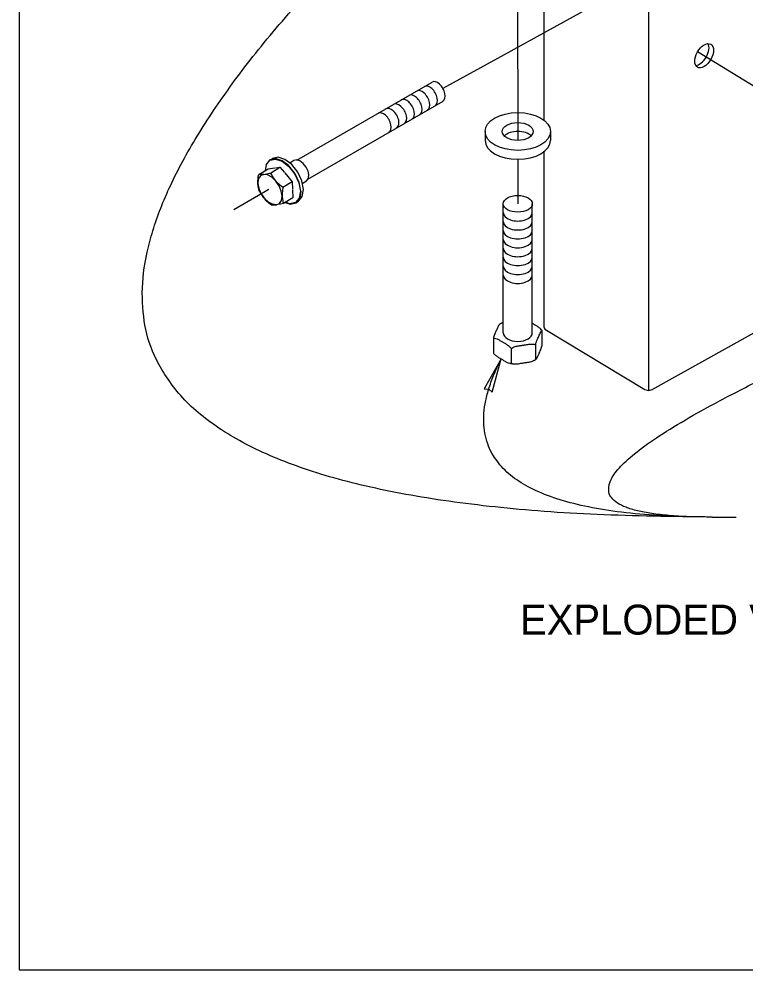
# Model space of a CAD drawing. Extents: x 99862 to 103151, y 99997 to 117076.
# Drawn here: x 99862 to 100348, y 112000 to 112634 of the extents above; entities that cross this region are included whole.
import ezdxf

# ---------------------------------------------------------------- set-up
doc = ezdxf.new("R2010")
doc.units = 0
for name, color, linetype in [('Level 1', 7, 'Continuous'), ('Level 12', 7, 'Continuous'), ('Level 13', 7, 'Continuous'), ('Level 15', 7, 'Continuous'), ('Level 20', 7, 'Continuous'), ('Level 3', 7, 'Continuous'), ('Level 4', 7, 'Continuous'), ('Level 5', 7, 'Continuous'), ('Level 60', 7, 'Continuous'), ('Level 9', 7, 'Continuous')]:
    doc.layers.add(name, color=color, linetype=linetype)

msp = doc.modelspace()

# ---------------------------------------------------------------- linework, layer by layer
at = {"layer": 'Level 1'}
msp.add_lwpolyline([(99862, 111999.5), (103151, 111999.5), (103151, 114075.5), (99862, 114075.5)], close=True, dxfattribs=at)
at = {"layer": 'Level 12'}
for p, q in [((100173.34, 112559.31), (100173.34, 112553.37)), ((100217.04, 112559.31), (100217.04, 112553.37)), ((100185.48, 112424.8), (100185.48, 112511.05)), ((100204.9, 112424.8), (100204.9, 112511.05)), ((100211.44, 112416.42), (100211.44, 112426.33)), ((100178.94, 112421.3), (100178.94, 112411.39)), ((100190.84, 112414.43), (100190.84, 112404.52)), ((100207.09, 112416.95), (100207.09, 112407.03))]:
    msp.add_line(p, q, dxfattribs=at)
for centre, major_axis in [((100195.19, 112559.31), (-21.85, 0)), ((100195.19, 112559.31), (-10.32, 0)), ((100195.19, 112511.05), (-9.71, 0))]:
    msp.add_ellipse(centre, major_axis=major_axis, ratio=0.57735, dxfattribs=at)
for centre, major_axis, start_param, end_param in [((100195.19, 112553.37), (-10.32, 0), 3.664192, 5.760586), ((100195.19, 112553.37), (21.85, 0), 3.141593, 6.283185), ((100195.19, 112505.1), (9.71, 0), 3.141588, 6.283185), ((100195.19, 112499.15), (9.71, 0), 3.141588, 6.283185), ((100195.19, 112493.2), (9.71, 0), 3.141588, 6.283185), ((100195.19, 112487.26), (9.71, 0), 3.141588, 6.283185), ((100195.19, 112481.31), (9.71, 0), 3.141588, 6.283185), ((100195.19, 112475.36), (9.71, 0), 3.141588, 6.283185), ((100195.19, 112469.41), (9.71, 0), 3.141588, 6.283185), ((100195.19, 112463.47), (9.71, 0), 3.141588, 6.283185), ((100195.19, 112424.8), (9.71, 0), 3.141593, 6.283185)]:
    msp.add_ellipse(centre, major_axis=major_axis, ratio=0.57735, start_param=start_param, end_param=end_param, dxfattribs=at)
for points, degree in [([(100185.48, 112431.72), (100185.12, 112431.6), (100184.77, 112431.47), (100184.27, 112431.24), (100184.08, 112431.15), (100183.9, 112431.05)], 3), ([(100183.17, 112430.63), (100183.11, 112430.6), (100183.05, 112430.54), (100182.43, 112429.88), (100181.71, 112428.26), (100181.12, 112426.98), (100180.53, 112425.69), (100179.81, 112424.24), (100179.15, 112422.09), (100179.04, 112421.7), (100178.94, 112421.3)], 3), ([(100183.9, 112431.05), (100183.68, 112430.93), (100183.47, 112430.81), (100183.23, 112430.67), (100183.2, 112430.65), (100183.17, 112430.63)], 3), ([(100211.44, 112426.33), (100211.18, 112426.67), (100210.88, 112427), (100209.07, 112428.77), (100207.12, 112429.81), (100205.49, 112430.75), (100205.3, 112430.86), (100205.1, 112430.97), (100204.9, 112431.09)], 3), ([(100207.09, 112416.95), (100207.18, 112417.34), (100207.29, 112417.74), (100207.96, 112419.89), (100208.67, 112421.34), (100209.26, 112422.62), (100209.86, 112423.9), (100210.57, 112425.53), (100211.23, 112426.23), (100211.35, 112426.32), (100211.44, 112426.33)], 3), ([(100178.94, 112421.3), (100179.2, 112421.35), (100179.51, 112421.32), (100181.32, 112421), (100183.27, 112419.79), (100184.89, 112418.85), (100186.52, 112417.91), (100188.46, 112416.87), (100190.27, 112415.11), (100190.58, 112414.78), (100190.84, 112414.43)], 3), ([(100190.84, 112414.43), (100191.19, 112414.68), (100191.61, 112414.9), (100194.08, 112416), (100196.74, 112416.33), (100198.96, 112416.68), (100201.18, 112417.02), (100203.84, 112417.52), (100206.32, 112417.18), (100206.73, 112417.09), (100207.09, 112416.95)], 3), ([(100207.21, 112407.08), (100207.27, 112407.12), (100207.34, 112407.17), (100207.96, 112407.84), (100208.67, 112409.46), (100209.26, 112410.74), (100209.86, 112412.02), (100210.57, 112413.47), (100211.23, 112415.62), (100211.35, 112416.02), (100211.44, 112416.42)], 3), ([(100178.94, 112411.39), (100179.2, 112411.04), (100179.51, 112410.71), (100181.32, 112408.95), (100183.27, 112407.91), (100184.89, 112406.97), (100186.49, 112406.04), (100188.41, 112404.86), (100189.93, 112404.56)], 3), ([(100192.18, 112404.21), (100194.25, 112403.98), (100196.81, 112404.46), (100198.96, 112404.79), (100201.18, 112405.13), (100203.84, 112405.46), (100206.12, 112406.48), (100206.3, 112406.57), (100206.49, 112406.67)], 3), ([(100206.49, 112406.66), (100206.71, 112406.78), (100206.92, 112406.9), (100207.15, 112407.04), (100207.18, 112407.06), (100207.21, 112407.08)], 3), ([(100189.93, 112404.56), (100190.68, 112404.41), (100191.44, 112404.3), (100192.18, 112404.21)], 2)]:
    msp.add_open_spline(points, degree=degree, dxfattribs=at)
at = {"layer": 'Level 13'}
for p, q in [((100047.6, 112540.08), (100137.95, 112592.24)), ((100054.88, 112527.47), (100145.25, 112579.64))]:
    msp.add_line(p, q, dxfattribs=at)
for centre, end_param in [((100136.45, 112582.97), 9.424783), ((100141.6, 112585.95), 9.429517), ((100126.14, 112577.02), 9.424778), ((100131.3, 112580), 9.424778), ((100115.84, 112571.07), 9.42478), ((100120.99, 112574.04), 9.424784), ((100105.53, 112565.12), 9.424778), ((100110.68, 112568.09), 9.424778)]:
    msp.add_ellipse(centre, major_axis=(3.64, -6.31), ratio=0.57735, start_param=6.283185, end_param=end_param, dxfattribs=at)
at = {"layer": 'Level 15'}
for p, q in [((100194.87, 112812.71), (100195.15, 112553.35)), ((100252.09, 112646.72), (100181.73, 112608.09)), ((100385.2, 112569.71), (100315.22, 112612.39)), ((100181.73, 112608.09), (100145.24, 112588.06)), ((100195.16, 112540.75), (100195.19, 112511.05)), ((100005.57, 112507.23), (100028.93, 112520.74)), ((100325.17, 112301.86), (100341.17, 112301.86))]:
    msp.add_line(p, q, dxfattribs=at)
msp.add_lwpolyline([(100184.09, 112407.43), (100172.64, 112387.45), (100175.8, 112387.29), (100178.16, 112385.18)], close=True, dxfattribs=at)
for points in [[(100325.17, 112301.86), (99735.04, 112301.86), (100059.37, 112657.5)], [(100325.17, 112301.86), (100130.24, 112301.86), (100184.09, 112407.43)], [(100325.17, 112301.86), (100160.65, 112301.86), (100386.47, 112407.43)]]:
    msp.add_open_spline(points, degree=2, dxfattribs=at)
at = {"layer": 'Level 3'}
for p, q in [((100027.09, 112537.06), (100029.53, 112540.04)), ((100029.57, 112539.98), (100029.53, 112540.04)), ((100033.31, 112540.81), (100033.29, 112540.87)), ((100037.78, 112539.37), (100037.78, 112539.42)), ((100027.05, 112537.32), (100026.39, 112533.23)), ((100042.32, 112535.88), (100042.33, 112535.92)), ((100029.66, 112531.46), (100029.76, 112531.42)), ((100046.22, 112530.87), (100046.25, 112530.89)), ((100048.89, 112525.11), (100048.93, 112525.11)), ((100047.05, 112511.65), (100049.53, 112514.68)), ((100049.24, 112514.9), (100049.24, 112514.9)), ((100050.3, 112519.43), (100049.53, 112514.68)), ((100049.93, 112519.47), (100049.98, 112519.45)), ((100043.01, 112511.02), (100043.03, 112510.96)), ((100046.75, 112511.85), (100046.78, 112511.79))]:
    msp.add_line(p, q, dxfattribs=at)
for points in [[(100029.53, 112540.35), (100027.05, 112537.32), (100027.06, 112537.32)], [(100033.34, 112541.19), (100029.53, 112540.35), (100029.53, 112540.35)], [(100029.56, 112539.98), (100029.53, 112540.04), (100033.29, 112540.87)], [(100033.3, 112540.81), (100033.29, 112540.87), (100037.78, 112539.42)], [(100037.91, 112539.72), (100033.34, 112541.19), (100033.35, 112541.19)], [(100037.77, 112539.37), (100037.78, 112539.42), (100042.33, 112535.92)], [(100042.03, 112536.54), (100037.91, 112539.72)], [(100027.14, 112537.01), (100027.09, 112537.06), (100026.49, 112533.29)], [(100042.31, 112535.89), (100042.33, 112535.92), (100046.25, 112530.89)], [(100046.21, 112530.88), (100046.25, 112530.89), (100048.93, 112525.11)], [(100048.88, 112525.12), (100048.93, 112525.11), (100049.98, 112519.45)], [(100049.22, 112514.77), (100046.78, 112511.79), (100043.03, 112510.96)], [(100049.93, 112519.49), (100049.98, 112519.45), (100049.22, 112514.77)], [(100050.26, 112519.43), (100050.27, 112519.43), (100050.27, 112519.43), (100050.3, 112519.43)], [(100039.71, 112511.94), (100043.24, 112510.81), (100043.24, 112510.81)], [(100043.02, 112511.02), (100043.03, 112510.96), (100039.8, 112512)], [(100043.24, 112510.81), (100047.05, 112511.65), (100047.05, 112511.65)]]:
    msp.add_lwpolyline(points, dxfattribs=at)
at = {"layer": 'Level 4'}
msp.add_line((100282.77, 112386.45), (100282.77, 112659.75), dxfattribs=at)
for points in [[(100212.71, 112651.71), (100212.71, 112566.85)], [(100212.71, 112545.82), (100212.71, 112428.94), (100213.27, 112427.31), (100279.99, 112387), (100282.77, 112386.45), (100285, 112387), (100353.39, 112425.13), (100355.06, 112427.85)]]:
    msp.add_lwpolyline(points, dxfattribs=at)
msp.add_ellipse((100319.68, 112609.84), major_axis=(-4.45, -7.71), ratio=0.57735, dxfattribs=at)
msp.add_ellipse((100316.66, 112611.58), major_axis=(4.45, 7.71), ratio=0.57735, start_param=3.487884, end_param=5.936894, dxfattribs=at)
at = {"layer": 'Level 5'}
for p, q in [((100029.92, 112540.43), (100031.27, 112541.26)), ((100049.45, 112514.71), (100049.47, 112514.72))]:
    msp.add_line(p, q, dxfattribs=at)
for points in [[(100047.31, 112511.96), (100048.75, 112512.85), (100051.23, 112515.86), (100051.99, 112520.58), (100050.93, 112526.28), (100048.21, 112532.1), (100044.25, 112537.15), (100039.63, 112540.67), (100035.08, 112542.11), (100031.27, 112541.26)], [(100051.25, 112524.59), (100054.05, 112526.32), (100055.23, 112527.76), (100055.6, 112530.02), (100055.56, 112530.57), (100055.09, 112532.75), (100053.79, 112535.53), (100051.89, 112537.95), (100049.68, 112539.63), (100047.5, 112540.32), (100045.68, 112539.92), (100042.88, 112538.19)], [(100049.56, 112514.83), (100049.56, 112514.84), (100050.33, 112519.55), (100049.27, 112525.26), (100046.55, 112531.08), (100042.58, 112536.13), (100042.03, 112536.54)], [(100039.7, 112511.94), (100039.72, 112511.92), (100040.01, 112511.85)]]:
    msp.add_lwpolyline(points, dxfattribs=at)
at = {"layer": 'Level 60'}
msp.add_line((99862, 111999.5), (99862, 111999.5), dxfattribs=at)
msp.add_line((99862, 111999.5), (99862, 111999.5), dxfattribs=at)
at = {"layer": 'Level 9'}
msp.add_line((100030.07, 112531.54), (100036.33, 112535.4), dxfattribs=at)
msp.add_line((100030.07, 112531.54), (100036.33, 112535.4), dxfattribs=at)
for points in [[(100021.57, 112525.13), (100021.57, 112525.25), (100021.82, 112528.54), (100021.85, 112528.96), (100022.13, 112530.61), (100028.39, 112534.46), (100032.85, 112534.99)], [(100021.57, 112525.13), (100021.57, 112525.25), (100021.82, 112528.54), (100021.85, 112528.96), (100022.13, 112530.61), (100028.39, 112534.46), (100032.85, 112534.99)], [(100033.26, 112535.04), (100036.33, 112535.4), (100039.37, 112531.83)], [(100033.26, 112535.04), (100036.33, 112535.4), (100039.37, 112531.83)], [(100025.23, 112530.63), (100023.28, 112529.74), (100022, 112527.81), (100021.57, 112525.13)], [(100025.23, 112530.63), (100023.28, 112529.74), (100022, 112527.81), (100021.57, 112525.13)], [(100025.57, 112530.67), (100025.23, 112530.63), (100024.78, 112530.58), (100023.17, 112530.56), (100022.78, 112530.55), (100022.13, 112530.61)], [(100025.57, 112530.67), (100025.23, 112530.63), (100024.78, 112530.58), (100023.17, 112530.56), (100022.78, 112530.55), (100022.13, 112530.61)], [(100032.11, 112528.06), (100033.39, 112526.39), (100030.83, 112528.79), (100028.09, 112530.29), (100025.57, 112530.67), (100026.47, 112530.8), (100028.44, 112531.21), (100030.07, 112531.54), (100031.22, 112529.59), (100032.11, 112528.06)], [(100032.11, 112528.06), (100033.39, 112526.39), (100030.83, 112528.79), (100028.09, 112530.29), (100025.57, 112530.67), (100026.47, 112530.8), (100028.44, 112531.21), (100030.07, 112531.54), (100031.22, 112529.59), (100032.11, 112528.06)], [(100039.52, 112531.65), (100044.56, 112525.72), (100044.7, 112520.83)], [(100039.52, 112531.65), (100044.56, 112525.72), (100044.7, 112520.83)], [(100021.57, 112525.13), (100021.59, 112524.63), (100021.73, 112523.05), (100022.06, 112521.61), (100022.43, 112520)], [(100022.43, 112520), (100022.06, 112521.61), (100021.73, 112523.05), (100021.59, 112524.63), (100021.57, 112525.13)], [(100021.59, 112524.63), (100022.18, 112521.38), (100023.62, 112517.98), (100025.7, 112514.91)], [(100021.59, 112524.63), (100022.18, 112521.38), (100023.62, 112517.98), (100025.7, 112514.91)], [(100044.56, 112525.72), (100038.3, 112521.87), (100036.86, 112523), (100036.46, 112523.38), (100033.78, 112525.94), (100033.58, 112526.17), (100033.39, 112526.39)], [(100044.56, 112525.72), (100038.3, 112521.87), (100036.86, 112523), (100036.46, 112523.38), (100033.78, 112525.94), (100033.58, 112526.17), (100033.39, 112526.39)], [(100033.93, 112510.36), (100035.97, 112511.21), (100037.33, 112513.19), (100037.75, 112516.07), (100037.19, 112519.49), (100035.71, 112523.04), (100033.58, 112526.17)], [(100033.93, 112510.36), (100035.97, 112511.21), (100037.33, 112513.19), (100037.75, 112516.07), (100037.19, 112519.49), (100035.71, 112523.04), (100033.58, 112526.17)], [(100044.71, 112520.44), (100044.86, 112515.11), (100038.6, 112511.26), (100036.78, 112510.88), (100035, 112510.51), (100033.93, 112510.36)], [(100044.71, 112520.44), (100044.86, 112515.11), (100038.6, 112511.26), (100036.78, 112510.88), (100035, 112510.51), (100033.93, 112510.36)], [(100038.3, 112521.87), (100038.01, 112519.7), (100037.8, 112518.14), (100037.77, 112516.08), (100037.77, 112515.77), (100038.19, 112512.88), (100038.24, 112512.52), (100038.6, 112511.26)], [(100038.3, 112521.87), (100038.01, 112519.7), (100037.8, 112518.14), (100037.77, 112516.08), (100037.77, 112515.77), (100038.19, 112512.88), (100038.24, 112512.52), (100038.6, 112511.26)], [(100025.99, 112514.56), (100025.7, 112514.91), (100025.56, 112515.07), (100023.54, 112518.04), (100023.24, 112518.48), (100022.43, 112520)], [(100025.99, 112514.56), (100025.7, 112514.91), (100025.56, 112515.07), (100023.54, 112518.04), (100023.24, 112518.48), (100022.43, 112520)], [(100025.99, 112514.56), (100027.4, 112513.07), (100028.97, 112511.75), (100030.66, 112510.33), (100031.31, 112510.26), (100031.77, 112510.25), (100031.8, 112510.24), (100033.93, 112510.36)], [(100033.93, 112510.36), (100031.39, 112510.67), (100028.61, 112512.15), (100025.99, 112514.56)], [(100033.93, 112510.36), (100031.39, 112510.67), (100028.61, 112512.15), (100025.99, 112514.56)], [(100033.93, 112510.36), (100031.8, 112510.24), (100031.77, 112510.25), (100031.31, 112510.26), (100030.66, 112510.33), (100028.97, 112511.75), (100027.4, 112513.07), (100025.99, 112514.56)]]:
    msp.add_lwpolyline(points, dxfattribs=at)

# ---------------------------------------------------------------- texts
at = {"layer": 'Level 20'}
msp.add_text('EXPLODED VIEW', height=20, dxfattribs=at).set_placement((100196.66, 112223.41))

doc.saveas('drawing.dxf')
